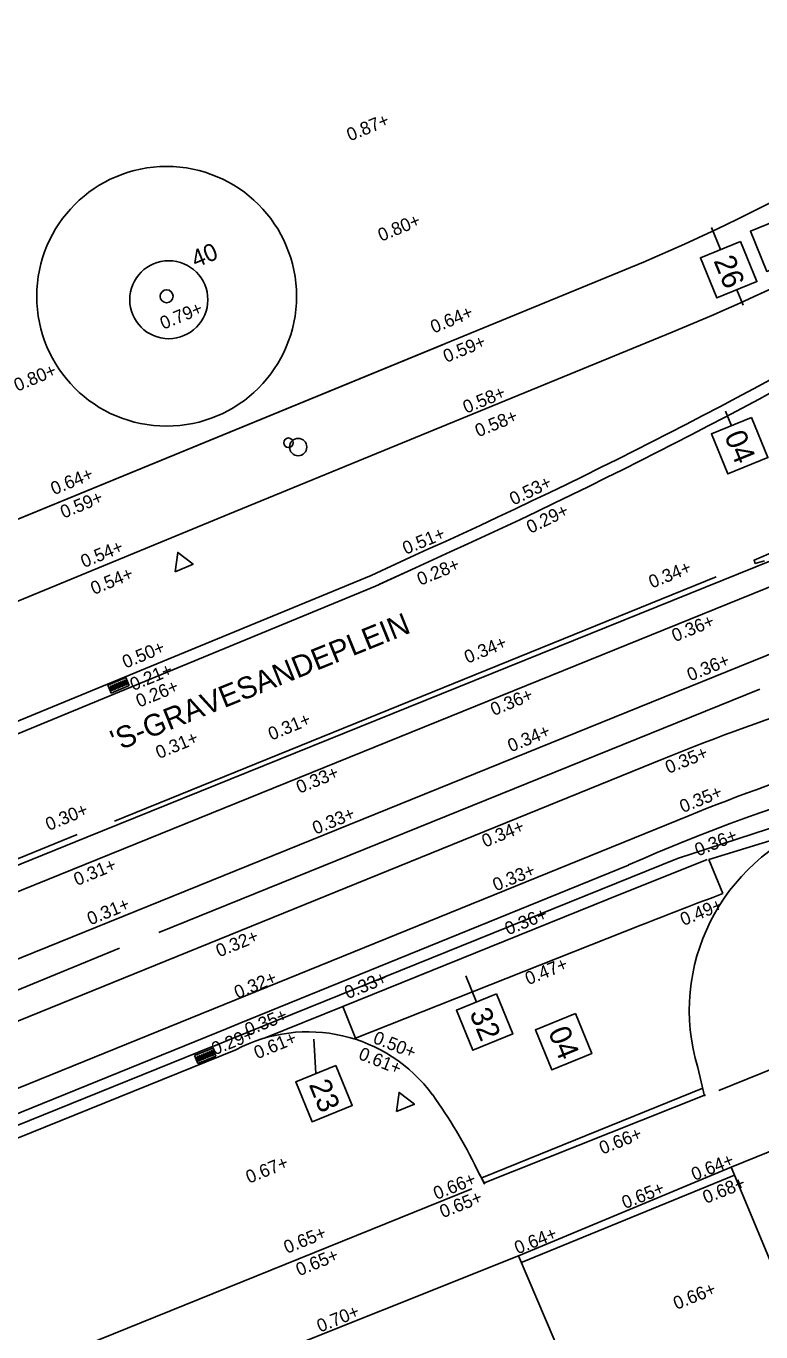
# Model space of a CAD drawing. Extents: x 122462 to 123306, y 485548 to 486417.
# Drawn here: x 122895.16 to 122912.13, y 485798.26 to 485828.43 of the extents above; entities that cross this region are included whole.
import ezdxf

# ---------------------------------------------------------------- set-up
doc = ezdxf.new("R2010")
doc.units = 0
for name, color, linetype in [('B-WE-GR-BOOM_BOOMDIAMETER', 7, 'Continuous'), ('B-WE-OG-HOOGTEPUNT-S', 7, 'Continuous'), ('B-WE-OG-TOPOGRAFIE_STRAATNAAM', 7, 'Continuous'), ('B-WE-RI-HWA_KOLK-S', 7, 'Continuous'), ('B-WE-VH-KANTOPSLUITING_TROTTOIRBAND_130 150-G', 7, 'Continuous'), ('B-WE-VH-KANTOPSLUITING_TROTTOIRBAND_280 300-G', 7, 'Continuous'), ('B-WE-VH-KANTOPSLUITING_TROTTOIRBAND_NATUURSTEEN_150-G', 7, 'Continuous'), ('B-WE-VH-KANTOPSLUITING_TROTTOIRBAND_NATUURSTEEN_300-G', 7, 'Continuous'), ('B-WE-VH-KANTVERHARDING_EIND_VERHARDING-G', 7, 'Continuous'), ('B-WE-VH-MATERIAALGRENS-G', 7, 'Continuous'), ('B-WE-VH-MATERIAALGRENS_ASFALT-G', 7, 'Continuous'), ('B-WE-VW-MARKERING_OVERIG-G', 7, 'Continuous'), ('iba7-verkeersbord rood', 7, 'Continuous'), ('V bss 4 strekken', 7, 'Continuous'), ('V Inritband 800x500 natuursteen', 7, 'Continuous'), ('V markering 1-1 10 cm', 7, 'Continuous'), ('V markering figuratie', 7, 'Continuous'), ('V markering ononderbroken streep 10 cm', 7, 'Continuous'), ('V materiaalscheiding algemeen', 7, 'Continuous'), ('V meubilair trammast', 7, 'Continuous'), ('V Rails', 7, 'Continuous'), ('V Trottoirband Natuursteen 150', 7, 'Continuous'), ('V Trottoirband Natuursteen 300', 7, 'Continuous'), ('X-WE-AL-TEKENBLAD-S', 7, 'Continuous')]:
    doc.layers.add(name, color=color, linetype=linetype)

msp = doc.modelspace()

# ---------------------------------------------------------------- linework, layer by layer
at = {"layer": 'B-WE-RI-HWA_KOLK-S'}
for p, q in [((122897.463, 485813.375), (122897.047, 485813.202)), ((122897.54, 485813.19), (122897.463, 485813.375)), ((122897.047, 485813.202), (122897.124, 485813.018)), ((122897.124, 485813.018), (122897.54, 485813.19)), ((122899.468, 485804.811), (122899.05, 485804.642)), ((122899.543, 485804.626), (122899.468, 485804.811)), ((122899.05, 485804.642), (122899.125, 485804.457)), ((122899.125, 485804.457), (122899.543, 485804.626))]:
    msp.add_line(p, q, dxfattribs=at)
for points in [[(122897.189, 485813.21), (122897.219, 485813.222), (122897.259, 485813.126), (122897.229, 485813.113), (122897.189, 485813.21)], [(122897.236, 485813.229), (122897.265, 485813.241), (122897.305, 485813.145), (122897.276, 485813.133), (122897.236, 485813.229)], [(122897.282, 485813.248), (122897.311, 485813.26), (122897.351, 485813.164), (122897.322, 485813.152), (122897.282, 485813.248)], [(122897.328, 485813.267), (122897.357, 485813.279), (122897.397, 485813.183), (122897.368, 485813.171), (122897.328, 485813.267)], [(122897.374, 485813.286), (122897.404, 485813.299), (122897.444, 485813.202), (122897.414, 485813.19), (122897.374, 485813.286)], [(122897.42, 485813.306), (122897.45, 485813.318), (122897.49, 485813.222), (122897.46, 485813.209), (122897.42, 485813.306)], [(122897.097, 485813.171), (122897.127, 485813.184), (122897.167, 485813.087), (122897.137, 485813.075), (122897.097, 485813.171)], [(122897.143, 485813.19), (122897.173, 485813.203), (122897.213, 485813.106), (122897.183, 485813.094), (122897.143, 485813.19)], [(122899.1, 485804.611), (122899.13, 485804.623), (122899.169, 485804.526), (122899.139, 485804.514), (122899.1, 485804.611)], [(122899.146, 485804.63), (122899.176, 485804.642), (122899.215, 485804.545), (122899.185, 485804.533), (122899.146, 485804.63)], [(122899.193, 485804.648), (122899.222, 485804.66), (122899.261, 485804.564), (122899.232, 485804.552), (122899.193, 485804.648)], [(122899.239, 485804.667), (122899.269, 485804.679), (122899.308, 485804.582), (122899.278, 485804.57), (122899.239, 485804.667)], [(122899.285, 485804.686), (122899.315, 485804.698), (122899.354, 485804.601), (122899.324, 485804.589), (122899.285, 485804.686)], [(122899.332, 485804.705), (122899.361, 485804.717), (122899.4, 485804.62), (122899.371, 485804.608), (122899.332, 485804.705)], [(122899.378, 485804.723), (122899.408, 485804.735), (122899.447, 485804.639), (122899.417, 485804.627), (122899.378, 485804.723)], [(122899.424, 485804.742), (122899.454, 485804.754), (122899.493, 485804.657), (122899.463, 485804.645), (122899.424, 485804.742)]]:
    msp.add_lwpolyline(points, dxfattribs=at)
at = {"layer": 'B-WE-VH-KANTOPSLUITING_TROTTOIRBAND_130 150-G'}
for points in [[(122876.646, 485807.539), (122881.26, 485809.455), (122892.404, 485814.087), (122899.856, 485817.162), (122910.084, 485821.354)], [(122875.333, 485787.496), (122876.312, 485787.868), (122893.962, 485794.992), (122906.533, 485800.012)]]:
    msp.add_lwpolyline(points, dxfattribs=at)
at = {"layer": 'B-WE-VH-KANTOPSLUITING_TROTTOIRBAND_280 300-G'}
for points in [[(122904.037, 485816.159), (122903.125, 485815.737), (122886.386, 485808.831), (122875.22, 485804.193)], [(122905.572, 485802.017), (122905.749, 485801.679)]]:
    msp.add_lwpolyline(points, dxfattribs=at)
for centre, radius, start, end in [((122901.671, 485801.62), 3.569, 36.2644, 117.9113), ((122894.747, 485796.718), 12.053, 26.081, 35.5807)]:
    msp.add_arc(centre, radius, start, end, dxfattribs=at)
at = {"layer": 'B-WE-VH-KANTOPSLUITING_TROTTOIRBAND_NATUURSTEEN_150-G'}
for points in [[(122909.42, 485822.971), (122889, 485814.585), (122876.031, 485809.199)], [(122876.646, 485807.539), (122881.26, 485809.455), (122892.404, 485814.087), (122899.856, 485817.162), (122910.084, 485821.354)], [(122904.776, 485821.064), (122889, 485814.585), (122876.031, 485809.199)], [(122917.092, 485806.239), (122911.156, 485803.833)], [(122911.44, 485802.059), (122917.748, 485804.62)], [(122905.454, 485801.56), (122875.291, 485789.351), (122874.354, 485788.962)], [(122875.333, 485787.496), (122876.312, 485787.868), (122893.962, 485794.992), (122906.533, 485800.012)]]:
    msp.add_lwpolyline(points, dxfattribs=at)
at = {"layer": 'B-WE-VH-KANTOPSLUITING_TROTTOIRBAND_NATUURSTEEN_300-G'}
for points in [[(122903.125, 485815.737), (122886.386, 485808.831), (122875.22, 485804.193)], [(122884.138, 485798.357), (122900, 485804.774)], [(122910.828, 485803.7), (122910.673, 485804.362)], [(122912.659, 485799.141), (122911.44, 485802.059)], [(122906.533, 485800.012), (122908.2, 485796.094)]]:
    msp.add_lwpolyline(points, dxfattribs=at)
at = {"layer": 'B-WE-VH-KANTVERHARDING_EIND_VERHARDING-G'}
msp.add_circle((122898.454, 485822.107), 0.901, dxfattribs=at)
at = {"layer": 'B-WE-VH-MATERIAALGRENS-G'}
for points in [[(122905.688, 485801.817), (122910.792, 485803.889)], [(122911.518, 485801.874), (122906.616, 485799.869)]]:
    msp.add_lwpolyline(points, dxfattribs=at)
at = {"layer": 'B-WE-VH-MATERIAALGRENS_ASFALT-G'}
for points in [[(122904.149, 485815.913), (122903.321, 485815.531)], [(122903.228, 485815.488), (122886.489, 485808.582), (122875.325, 485803.944)], [(122899.492, 485804.859), (122899.899, 485805.024)], [(122910.851, 485803.731), (122905.723, 485801.691)], [(122906.533, 485800.012), (122911.44, 485802.059)]]:
    msp.add_lwpolyline(points, dxfattribs=at)
at = {"layer": 'B-WE-VW-MARKERING_OVERIG-G'}
for centre, radius in [((122901.218, 485818.801), 0.11), ((122901.442, 485818.702), 0.2)]:
    msp.add_circle(centre, radius, dxfattribs=at)
at = {"layer": 'iba7-verkeersbord rood'}
for radius in [3, 0.15]:
    msp.add_circle((122898.404, 485822.185), radius, dxfattribs=at)
for start, end in [(0, 180), (180, 0)]:
    msp.add_arc((122898.404, 485822.185), 0.15, start, end, dxfattribs=at)
at = {"layer": 'V bss 4 strekken'}
msp.add_lwpolyline([(122904.149, 485815.913), (122903.228, 485815.488)], dxfattribs=at)
msp.add_arc((122853.766, 485928.547), 123.389, 294.10001, 300.67146, dxfattribs=at)
at = {"layer": 'V Inritband 800x500 natuursteen'}
msp.add_line((122911.253, 485808.386), (122910.926, 485809.174), dxfattribs=at)
for points in [[(122902.475, 485805.775), (122908.605, 485808.255), (122910.892, 485809.174)], [(122902.475, 485805.775), (122902.764, 485805.045), (122909.36, 485807.652)]]:
    msp.add_lwpolyline(points, dxfattribs=at)
msp.add_arc((122956.161, 485689.76), 126.841, 110.73495, 111.65209, dxfattribs=at)
at = {"layer": 'V markering 1-1 10 cm'}
for points in [[(122897.197, 485810.058), (122911.094, 485815.706)], [(122912.107, 485813.107), (122898.227, 485807.487)]]:
    msp.add_lwpolyline(points, dxfattribs=at)
at = {"layer": 'V markering figuratie'}
for points in [[(122911.995, 485816.009), (122911.971, 485816.086), (122913.478, 485816.734)], [(122911.995, 485816.009), (122912.217, 485816.073)]]:
    msp.add_lwpolyline(points, dxfattribs=at)
at = {"layer": 'V markering ononderbroken streep 10 cm'}
for points in [[(122882.925, 485804.264), (122896.336, 485809.75)], [(122897.315, 485807.119), (122883.989, 485801.64)]]:
    msp.add_lwpolyline(points, dxfattribs=at)
at = {"layer": 'V materiaalscheiding algemeen'}
for points in [[(122913.537, 485816.549), (122903.989, 485812.694), (122896.562, 485809.691), (122891.018, 485807.44), (122891.755, 485805.559)], [(122910.203, 485809.196), (122914.409, 485810.565)], [(122910.926, 485809.174), (122913.017, 485809.811)], [(122899.799, 485805.268), (122900.078, 485805.382), (122909.07, 485809.044)], [(122899.899, 485805.024), (122910.203, 485809.196)], [(122900.679, 485805.048), (122902.475, 485805.775)], [(122894.326, 485803.642), (122894.545, 485803.131), (122899.799, 485805.268)], [(122887.715, 485800.095), (122899.48, 485804.855)]]:
    msp.add_lwpolyline(points, dxfattribs=at)
msp.add_arc((122926.948, 485768.416), 44.388, 98.7738, 113.7509, dxfattribs=at)
at = {"layer": 'V meubilair trammast'}
for points in [[(122898.601, 485815.82), (122899.016, 485815.993), (122898.659, 485816.266)], [(122903.71, 485803.345), (122904.127, 485803.514), (122903.772, 485803.791)]]:
    msp.add_lwpolyline(points, close=True, dxfattribs=at)
at = {"layer": 'V Rails'}
for p, q in [((122913.713, 485816.028), (122883.169, 485803.647)), ((122914.253, 485814.694), (122883.711, 485802.313)), ((122886.88, 485802.155), (122909.899, 485811.507)), ((122887.421, 485800.82), (122910.441, 485810.173))]:
    msp.add_line(p, q, dxfattribs=at)
for radius in [46.552, 45.112]:
    msp.add_arc((122927.51, 485768.415), radius, 102.4046, 112.2312, dxfattribs=at)
at = {"layer": 'V Trottoirband Natuursteen 150'}
for centre, radius, start, end in [((122889.885, 485868.455), 49.501, 293.2433, 306.0415), ((122890.369, 485869.117), 51.672, 292.4294, 301.5945)]:
    msp.add_arc(centre, radius, start, end, dxfattribs=at)
at = {"layer": 'V Trottoirband Natuursteen 300'}
for points in [[(122904.037, 485816.159), (122903.125, 485815.737)], [(122905.572, 485802.017), (122905.755, 485801.668)]]:
    msp.add_lwpolyline(points, dxfattribs=at)
for centre, radius, start, end in [((122853.769, 485928.556), 123.126, 294.09587, 300.66803), ((122915.064, 485805.684), 4.586, 110.1855, 196.7612), ((122901.671, 485801.62), 3.569, 36.2644, 117.9113), ((122894.747, 485796.718), 12.053, 26.081, 35.5807)]:
    msp.add_arc(centre, radius, start, end, dxfattribs=at)
at = {"layer": 'X-WE-AL-TEKENBLAD-S'}
for p, q in [((122911.197, 485823.263), (122910.988, 485823.777)), ((122911.575, 485822.337), (122911.72, 485821.982)), ((122911.452, 485819.195), (122911.315, 485819.532)), ((122905.559, 485805.878), (122905.313, 485806.481)), ((122901.849, 485804.225), (122901.803, 485805.016))]:
    msp.add_line(p, q, dxfattribs=at)
for points in [[(122912.814, 485824.065), (122913.192, 485823.139), (122912.266, 485822.762), (122911.888, 485823.688)], [(122911.66, 485823.452), (122912.038, 485822.526), (122911.112, 485822.149), (122910.734, 485823.075)], [(122911.915, 485819.384), (122912.293, 485818.458), (122911.367, 485818.08), (122910.989, 485819.006)], [(122906.022, 485806.066), (122906.4, 485805.14), (122905.474, 485804.763), (122905.096, 485805.689)], [(122907.847, 485805.612), (122908.225, 485804.686), (122907.299, 485804.308), (122906.921, 485805.234)], [(122902.312, 485804.414), (122902.69, 485803.488), (122901.764, 485803.11), (122901.387, 485804.036)]]:
    msp.add_lwpolyline(points, close=True, dxfattribs=at)

# ---------------------------------------------------------------- texts
at = {"layer": 'B-WE-GR-BOOM_BOOMDIAMETER'}
msp.add_text('40', height=0.4, rotation=22.3273, dxfattribs=at).set_placement((122899.076, 485822.84))
at = {"layer": 'B-WE-OG-HOOGTEPUNT-S'}
for s, rotation, p in [('0.87+', 22.3273, (122902.638, 485825.763)), ('0.80+', 22.3273, (122903.36, 485823.445)), ('0.79+', 22.3273, (122898.327, 485821.411)), ('0.64+', 22.3273, (122904.573, 485821.323)), ('0.59+', 22.3273, (122904.866, 485820.645)), ('0.80+', 22.5564, (122894.953, 485819.978)), ('0.58+', 22.3273, (122905.323, 485819.47)), ('0.58+', 22.3273, (122905.603, 485818.925)), ('0.64+', 22.3273, (122895.801, 485817.587)), ('0.53+', 25.7427, (122906.415, 485817.347)), ('0.59+', 22.3273, (122896.024, 485817.046)), ('0.29+', 25.7427, (122906.807, 485816.696)), ('0.51+', 22.3273, (122903.928, 485816.21)), ('0.54+', 22.3273, (122896.495, 485815.905)), ('0.28+', 22.3273, (122904.264, 485815.495)), ('0.34+', 21.9864, (122909.613, 485815.431)), ('0.54+', 22.3273, (122896.724, 485815.283)), ('0.36+', 21.9864, (122910.145, 485814.192)), ('0.50+', 22.3273, (122897.454, 485813.581)), ('0.34+', 22.2492, (122905.354, 485813.693)), ('0.36+', 21.9864, (122910.498, 485813.285)), ('0.21+', 22.3273, (122897.633, 485813.063)), ('0.26+', 22.3273, (122897.771, 485812.679)), ('0.36+', 22.2492, (122905.958, 485812.486)), ('0.31+', 22.2492, (122900.824, 485811.917)), ('0.31+', 22.3273, (122898.226, 485811.49)), ('0.34+', 22.2492, (122906.356, 485811.646)), ('0.35+', 22.043, (122909.996, 485811.148)), ('0.33+', 22.2492, (122901.473, 485810.688)), ('0.35+', 22.043, (122910.327, 485810.242)), ('0.30+', 22.2492, (122895.68, 485809.829)), ('0.33+', 22.2492, (122901.846, 485809.742)), ('0.34+', 22.2492, (122905.758, 485809.444)), ('0.36+', 22.043, (122910.676, 485809.239)), ('0.31+', 22.2492, (122896.333, 485808.557)), ('0.33+', 22.2492, (122906.01, 485808.432)), ('0.31+', 22.2492, (122896.643, 485807.647)), ('0.49+', 22.043, (122910.34, 485807.633)), ('0.36+', 22.043, (122906.29, 485807.417)), ('0.32+', 22.2492, (122899.618, 485806.907)), ('0.47+', 22.043, (122906.758, 485806.265)), ('0.32+', 22.2492, (122900.039, 485805.947)), ('0.33+', 22.0267, (122902.586, 485805.943)), ('0.35+', 22.2492, (122900.284, 485805.086)), ('0.29+', 22.0252, (122899.514, 485804.645)), ('0.61+', 22.2492, (122900.496, 485804.553)), ('0.50+', 338.12, (122903.149, 485804.941)), ('0.61+', 338.12, (122902.813, 485804.569)), ('0.66+', 21.6934, (122908.469, 485802.35)), ('0.67+', 22.0365, (122900.307, 485801.678)), ('0.64+', 21.6934, (122910.595, 485801.743)), ('0.66+', 21.6934, (122904.637, 485801.303)), ('0.68+', 21.6934, (122910.859, 485801.212)), ('0.65+', 21.6934, (122904.783, 485800.881)), ('0.65+', 21.6934, (122908.989, 485801.091)), ('0.65+', 22.0365, (122901.183, 485800.057)), ('0.64+', 21.6934, (122906.509, 485800.044)), ('0.65+', 22.0365, (122901.465, 485799.54)), ('0.66+', 21.6934, (122910.179, 485798.763)), ('0.70+', 22.0365, (122901.947, 485798.238))]:
    msp.add_text(s, height=0.3, rotation=rotation, dxfattribs=at).set_placement(p)
at = {"layer": 'B-WE-OG-TOPOGRAFIE_STRAATNAAM'}
msp.add_text("'S-GRAVESANDEPLEIN", height=0.5, rotation=22.0252, dxfattribs=at).set_placement((122897.236, 485811.657))
at = {"layer": 'X-WE-AL-TEKENBLAD-S'}
for s, p in [('26', (122911.031, 485823.009)), ('04', (122911.277, 485818.964)), ('32', (122905.392, 485805.624)), ('04', (122907.209, 485805.192)), ('23', (122901.683, 485803.972))]:
    msp.add_text(s, height=0.5, rotation=292.187, dxfattribs=at).set_placement(p)

doc.saveas('drawing.dxf')
